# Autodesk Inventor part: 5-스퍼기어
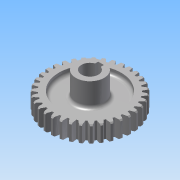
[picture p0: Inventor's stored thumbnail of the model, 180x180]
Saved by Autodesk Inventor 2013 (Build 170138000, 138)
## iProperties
Created: 2013-08
Part Number: 5-스퍼기어
Material: 강
Document SubType Name: Modeling
Designer: 한국산업디자인학원
Categories: <?xml version="1.0" encoding="UTF-16"?> <MemberInstance><Categories><FamilyTemplate><FamilyTemplateParameter ValueType="xs:double" Id="1" ObjectReferenceKey="da
Density: 1 g/cm^3
CustomPartVersion: 1
Author: 한국산업디자인학원
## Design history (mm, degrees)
sketch "Sketch1"
  geometry: C1 r 37 at (0, 0)
  constraints: 1 centre point
  dimensions: "d0" = 74 diameter of C1 (= da_da)
extrude "Extrusion1" new body sketch "Sketch1" distance "d1" = 15 (= da_b); taper "d2" = 0 deg
chamfer "모따기1" distance "d49" = 1; stored, may be unused: second distance "d50" = 2, angle "d51" = 45 deg
feature "피치 지름" dims "d4" = 10, "d5" = 0
workplane "Work Plane8"
workplane "Work Plane9"
sketch "스케치3"
  geometry: C1 r 36 at (0, 0) reference; C2 r 27.5 at (0, 0); C3 r 12.5 at (0, 0)
  constraints: 2 centre point, 2 coincident
  dimensions: "d52" = 55 diameter of C2; "d54" = 25 diameter of C3
extrude "돌출2" cut sketch "스케치3" distance "d55" = 5; taper "d56" = 0 deg
sketch "스케치4"
  geometry: C1 r 36 at (0, 0) reference; C2 r 27.5 at (0, 0); C3 r 12.5 at (0, 0)
  constraints: 2 centre point, 2 coincident
  dimensions: "d57" = 55 diameter of C2; "d59" = 25 diameter of C3
extrude "돌출3" cut sketch "스케치4" distance "d60" = 5; taper "d61" = 0 deg
node "작업 평면11"
sketch "스케치6"
  geometry: C1 r 12.5 at (0, 0) reference; 1 further point
extrude "돌출5" join sketch "스케치6" stored distance "d78" = 5; taper "d79" = 0 deg
feature "스퍼 기어" dims "da_b" = 15, "da_d" = 70, "da_aw" = 70, "da_da" = 74, "da_df" = 65, "da_dw" = 70, angle "da_beta" = 0 deg, "da_lefttooth" = 0, "da_righttooth" = 0
fillet "모깎기1" dims "d76" = 3
sketch "스케치10"
  geometry: L1 (-2.5, 7.071)-(-2.5, 9.8); L2 (-2.5, 9.8)-(2.5, 9.8); L3 (2.5, 9.8)-(2.5, 7.071); C1 r 12.5 at (0, 0) reference; A1 r 7.5 centre (0, 0) between (-2.5, 7.071) and (2.5, 7.071)
  constraints: 6 end point, 2 parallel, 2 point on circle, 1 centre point, 1 coincident, 1 perpendicular, 1 vertical
  dimensions: "d94" = 15 diameter of A1; "d96" = 5 distance of L1.end L2.end; "d97" = 17.3 dimension on A1 L2
extrude "돌출7" cut sketch "스케치10" stored distance "d98" = 10; taper "d99" = 0 deg
body "Solid1"
sketch "Sketch2"
  geometry: C1 r 37 at (0, 0) reference; C2 r 35 at (0, 0)
  constraints: 1 centre point, 1 coincident
  dimensions: "d3" = 70 diameter of C2 (= da_dw)
body "Srf1"
node "투영된 루프1"
other parameters: "d34" = 0.8976 (computed from da_z), "d39" = 0, "d41" = 0, "d47" = 0, "d48" = 0, "d77" = 31
